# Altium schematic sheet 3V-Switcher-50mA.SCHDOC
size A4; Organization: UNSW Solar Racing Team; Address3: UNSW; Address4: Sydney NSW 2052; Address2: Electrical Engineering; Address1: Rm 109
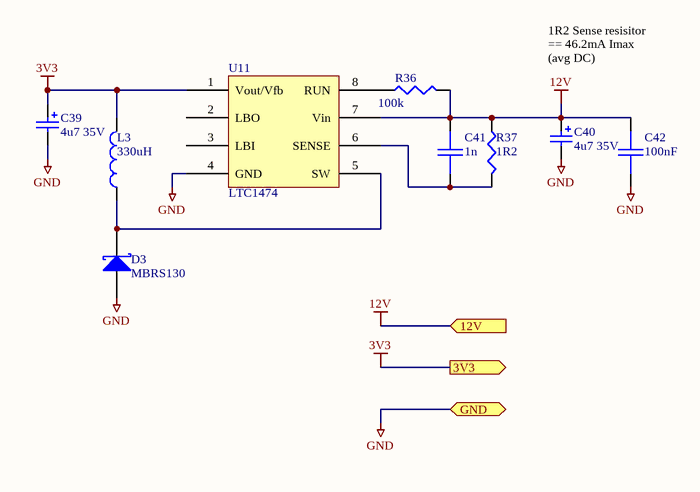
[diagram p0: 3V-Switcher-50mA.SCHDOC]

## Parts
C39  4u7 35V  [MCCT-CASEC]
C40  4u7 35V  [MCCT-CASEC]
C41  1n  [0603]
C42  100nF  [0603]
D3  MBRS130  [SMB]
L3  330uH  [1812]
R36  100k  [0603]
R37  1R2  [0603]
U11  LTC1474  [TSOP8]

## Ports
3V3 (out), 12V (in), GND (bidir)

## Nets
3V3: C39.1 L3.2 U11.1(Vout/Vfb) ; port 3V3
12V: C40.1 C41.1 C42.1 R36.2 R37.1 U11.7(Vin) ; port 12V
GND: C39.2 C40.2 C42.2 D3.A U11.4(GND) ; port GND
NetC41_2: C41.2 R37.2 U11.6(SENSE)
NetD3_K: D3.K L3.1 U11.5(SW)
NetR36_1: R36.1 U11.8(RUN)

Not connected (* = marked no-connect by the designer): U11 2(LBO) 3(LBI)

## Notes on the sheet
- 1R2 Sense resisitor == 46.2mA Imax (avg DC)

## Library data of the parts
C39 C40 = Cap Pol3: Polarized Capacitor (Surface Mount); Value: 4.7uF; Order#: 197-609
C41 = CAP: Capacitor; Value: 1nF; Order#: 317-202
C42 = CAP: Capacitor; Value: 0.1uF; Order#: 753-567
D3 = D SCHOTTKY: Schottky Diode; Order#: 9556931
L3 = Inductor: Order#: 8808538
R36 = RES1: Resistor; Order#: 933-3738
R37 = RES1: Resistor; Value: 1.2R; Order#: 139-9658
U11 = LTC1474: Step-down converter; Order#: LTC1474CMS8-3.3-ND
